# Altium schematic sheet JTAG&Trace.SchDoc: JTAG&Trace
size A3; DocumentNumber: MB1144; Revision: C-02; SheetNumber: 24; SheetTotal: 25; Project: STM32L476G-EVAL
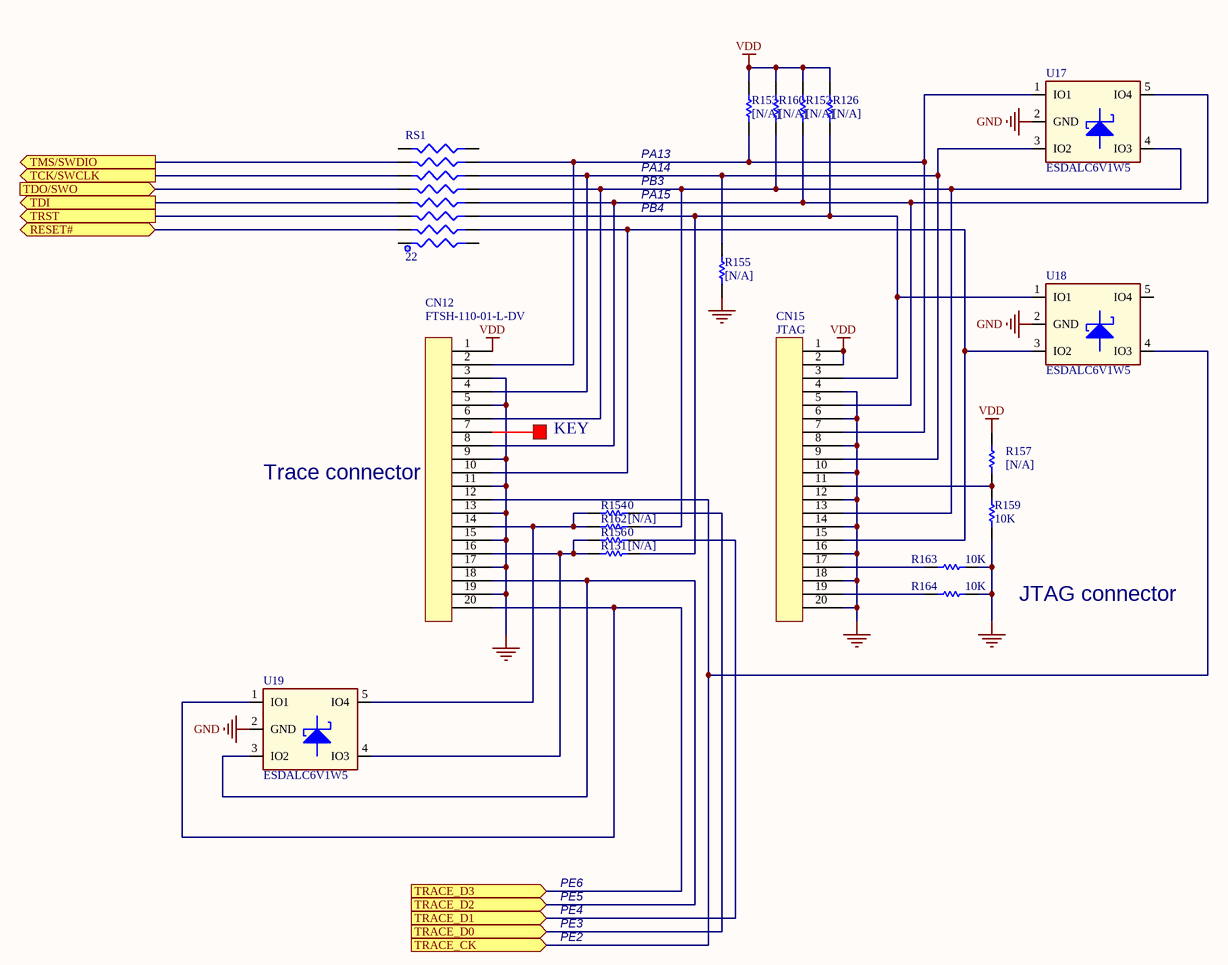
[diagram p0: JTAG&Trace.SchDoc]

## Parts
CN12  FTSH-110-01-L-DV  [FTSH-110-01-L-DV]
CN15  JTAG  [IDC20S]
R126  [N/A]  [0603R]
R131  [N/A]  [0603R]
R152  [N/A]  [0603R]
R153  [N/A]  [0603R]
R154  0  [0603R]
R155  [N/A]  [0603R]
R156  0  [0603R]
R157  [N/A]  [0603R]
R159  10K  [0402R]
R160  [N/A]  [0603R]
R162  [N/A]  [0603R]
R163  10K  [0402R]
R164  10K  [0402R]
RS1  22  [RP0402X8_REV]
U17  ESDALC6V1W5  [SOT-353]
U18  ESDALC6V1W5  [SOT-353]
U19  ESDALC6V1W5  [SOT-353]

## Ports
RESET# (bidir), TCK/SWCLK (out), TDI (out), TDO/SWO (in), TMS/SWDIO (out), TRACE_CK (in), TRACE_D0 (in), TRACE_D1 (in), TRACE_D2 (in), TRACE_D3 (in), TRST (out)

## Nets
GND: CN12.3 CN12.5 CN12.9 CN12.11 CN12.13 CN12.15 CN12.17 CN12.19 CN15.4 CN15.6 CN15.8 CN15.10 CN15.12 CN15.14 CN15.16 CN15.18 CN15.20 R155.1 R159.1 R163.1 R164.1 U17.2(GND) U18.2(GND) U19.2(GND)
VDD: CN12.1 CN15.1 CN15.2 R126.2 R152.2 R153.2 R157.2 R160.2
RESET#: RS1.3 ; port RESET#
TCK/SWCLK: RS1.11 ; port TCK/SWCLK
TDI: RS1.7 ; port TDI
TDO/SWO: RS1.9 ; port TDO/SWO
TMS/SWDIO: RS1.13 ; port TMS/SWDIO
TRACE_CK: CN12.12 U18.4(IO3) ; port TRACE_CK
TRACE_D0: R154.2 ; port TRACE_D0
TRACE_D1: R156.2 ; port TRACE_D1
TRACE_D2: CN12.18 U19.3(IO2) ; port TRACE_D2
TRACE_D3: CN12.20 U19.1(IO1) ; port TRACE_D3
TRST: RS1.5 ; port TRST
NetCN12_2: CN12.2 CN15.7 R153.1 RS1.14 U17.1(IO1)
NetCN12_4: CN12.4 CN15.9 R155.2 RS1.12 U17.3(IO2)
NetCN12_6: CN12.6 CN15.13 R160.1 R162.2 RS1.10 U17.4(IO3)
NetCN12_8: CN12.8 CN15.5 R152.1 RS1.8 U17.5(IO4)
NetCN12_10: CN12.10 CN15.15 RS1.4 U18.3(IO2)
NetCN12_14: CN12.14 R154.1 R162.1 U19.5(IO4)
NetCN12_16: CN12.16 R131.1 R156.1 U19.4(IO3)
NetCN15_3: CN15.3 R126.1 R131.2 RS1.6 U18.1(IO1)
NetCN15_11: CN15.11 R157.1 R159.2
NetCN15_17: CN15.17 R163.2
NetCN15_19: CN15.19 R164.2

Not connected (* = marked no-connect by the designer): CN12 7; RS1 1 2 15 16; U18 5(IO4)

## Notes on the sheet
- PA13
- PA14
- PB3
- PA15
- PB4
- (near CN12) Trace connector
- KEY
- JTAG connector
- PE6
- PE5
- PE4
- PE3
- PE2

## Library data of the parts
CN12 = 20PIN1: Ordered by: Subcon; Comments: Trace connector; Assembly: with pin7 removed; ECCN_US/EU: NA
CN15 = 20PIN1: Ordered by: Subcon; Comments: JTAG connector; ECCN_US/EU: NA
R126 R131 R152 R153 R155 R157 R160 R162 = Res1: Resistor; Value: 1K; Ordered by: Subcon; ECCN_US/EU: NA; Fitted: NO
R154 R156 R159 R163 R164 = Res1: Resistor; Value: 1K; Ordered by: Subcon; ECCN_US/EU: NA
RS1 = RES8B: Ordered by: Subcon; ECCN_US/EU: NA
U17-U19 = ESDALC6V1W5: Dual Transil array for ESD protection; Manuf_1: ST; Ref St: 9151112; Order: ESDA5V3L; ECCN_US/EU: EAR99/NEC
